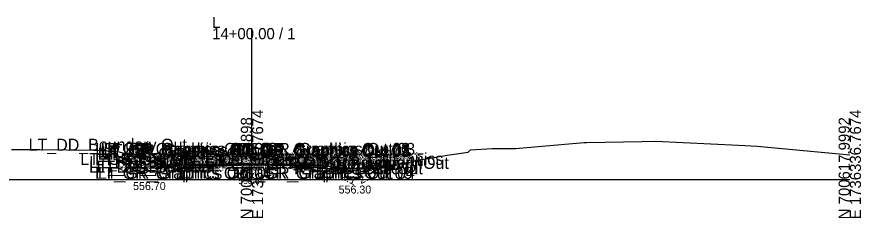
# Model space of a CAD drawing. Extents: x -26 to 697, y -10 to 2642.
# Drawn here: x 91 to 302.8, y 2390.3 to 2440.7 of the extents above; entities that cross this region are included whole.
import ezdxf

# ---------------------------------------------------------------- set-up
doc = ezdxf.new("R2010")
doc.units = 0
for name, color, linetype in [('Default', 7, 'Continuous'), ('Exist CMT Pavement', 7, 'Continuous'), ('Exist Cross Section Cell', 7, 'Continuous'), ('Exist XS Center Line Elevation Label', 7, 'Continuous'), ('Exist XS Ground Line', 7, 'Continuous'), ('Prop CMT Ditch DDE', 7, 'Continuous'), ('Prop CMT Guardrail Graphics', 7, 'Continuous'), ('Prop CMT Pvmt Course 1', 7, 'Continuous'), ('Prop CMT Pvmt Course 1 Wedge', 7, 'Continuous'), ('Prop CMT Pvmt Course 2', 7, 'Continuous'), ('Prop CMT Pvmt Course 2 Wedge', 7, 'Continuous'), ('Prop CMT Pvmt Surface', 7, 'Continuous'), ('Prop CMT Pvmt Surface Shoulder', 7, 'Continuous'), ('Prop CMT Pvmt Wedge Surface 1', 7, 'Continuous'), ('Prop CMT Pvmt Wedge Surface 2', 7, 'Continuous'), ('Prop CMT Shld Paved Course 1', 7, 'Continuous'), ('Prop CMT Shld Paved Course 2', 7, 'Continuous'), ('Prop CMT Slope Grass', 7, 'Continuous'), ('Prop CMT Subgrade Earthwork', 7, 'Continuous'), ('Prop XS Ditch Slope Text', 7, 'Continuous'), ('Prop XS Ditch Standard Text', 7, 'Continuous'), ('Prop XS SE Text', 7, 'Continuous'), ('Prop XS Side Slope Text', 7, 'Continuous'), ('Scratch_Level_1', 7, 'Continuous')]:
    doc.layers.add(name, color=color, linetype=linetype)

msp = doc.modelspace()

# ---------------------------------------------------------------- linework, layer by layer
at = {"layer": 'Exist CMT Pavement'}
for points in [[(150, 2403.64), (140.23, 2403.41)], [(140.23, 2403.41), (145.12, 2403.54)], [(145.12, 2403.54), (150, 2403.64)], [(154.78, 2403.6), (150, 2403.64)], [(150, 2403.64), (159.56, 2403.56)], [(159.56, 2403.56), (154.78, 2403.6)]]:
    msp.add_lwpolyline(points, dxfattribs=at)
at = {"layer": 'Exist Cross Section Cell'}
for p, q in [((150, 2400), (150, 2437.94)), ((0, 2400), (150, 2400)), ((150, 2400), (300, 2400))]:
    msp.add_line(p, q, dxfattribs=at)
at = {"layer": 'Exist XS Ground Line'}
msp.add_lwpolyline([(89.62, 2407.5), (96.35, 2407.5), (96.79, 2407.48), (110.3, 2407.33), (113.86, 2407.2), (116.66, 2406.93), (126.39, 2404.1), (132.44, 2402.17), (133.66, 2402.5), (135.83, 2403.03), (138.5, 2403.21), (140.23, 2403.41), (147.33, 2403.6), (149.81, 2403.64), (152.37, 2403.62), (159.56, 2403.56), (161.48, 2403.39), (162.65, 2403.28), (163.39, 2403.11), (167.5, 2402), (170.95, 2402.75), (171.39, 2402.77), (181, 2402.6), (190.42, 2404.47), (191.73, 2404.87), (193.73, 2405.2), (198.95, 2406.12), (204.27, 2406.86), (204.81, 2407.38), (210.28, 2407.71), (216.16, 2407.72), (232.35, 2409.18), (233.37, 2409.22), (234.04, 2409.25), (247.79, 2409.53), (251.23, 2409.57), (272.11, 2408.62), (276.72, 2408.36), (300, 2406.19)], dxfattribs=at)
at = {"layer": 'Prop CMT Ditch DDE'}
for points in [[(124.63, 2401.7), (113.62, 2407.2)], [(130.01, 2402.95), (127.01, 2402.89), (124.63, 2401.7)], [(170.58, 2402.67), (173.58, 2402.61), (176.2, 2401.3)], [(176.2, 2401.3), (178.88, 2402.64)], [(124.63, 2401.7), (124.63, 2401.7)], [(176.2, 2401.3), (176.2, 2401.3)]]:
    msp.add_lwpolyline(points, dxfattribs=at)
at = {"layer": 'Prop CMT Guardrail Graphics'}
for points in [[(132.33, 2400.15), (132.33, 2406.15)], [(132.33, 2406.15), (133.66, 2406.15), (133.93, 2405.86)], [(133.93, 2405.27), (133.66, 2404.98), (132.99, 2404.98)], [(132.99, 2404.98), (132.99, 2400.15)], [(133.93, 2405.86), (133.66, 2405.57)], [(133.66, 2405.57), (133.93, 2405.27)], [(167.71, 2406.15), (166.38, 2406.15), (166.11, 2405.86)], [(166.11, 2405.86), (166.38, 2405.57)], [(166.38, 2405.57), (166.11, 2405.27)], [(166.11, 2405.27), (166.38, 2404.98), (167.04, 2404.98)], [(167.04, 2404.98), (167.04, 2400.15)], [(167.71, 2400.15), (167.71, 2406.15)], [(132.99, 2400.15), (132.33, 2400.15)], [(167.04, 2400.15), (167.71, 2400.15)]]:
    msp.add_lwpolyline(points, dxfattribs=at)
at = {"layer": 'Prop CMT Pvmt Course 1'}
for points in [[(150, 2403.97), (139, 2403.75)], [(139, 2403.75), (139, 2403.54)], [(139, 2403.54), (140.23, 2403.57)], [(140.23, 2403.67), (150, 2403.87)], [(140.23, 2403.57), (140.23, 2403.67)], [(150, 2403.76), (150, 2403.97)], [(150, 2403.97), (161, 2403.75)], [(150, 2403.76), (150, 2403.97)], [(150, 2403.87), (150, 2403.76), (150, 2403.76)], [(159.56, 2403.68), (150, 2403.87)], [(150, 2403.87), (150, 2403.76), (150, 2403.76)], [(159.56, 2403.57), (159.56, 2403.68)], [(161, 2403.54), (159.56, 2403.57)], [(161, 2403.75), (161, 2403.54)]]:
    msp.add_lwpolyline(points, dxfattribs=at)
at = {"layer": 'Prop CMT Pvmt Course 1 Wedge'}
for points in [[(150, 2403.87), (140.23, 2403.67)], [(150, 2403.87), (159.56, 2403.68)]]:
    msp.add_lwpolyline(points, dxfattribs=at)
at = {"layer": 'Prop CMT Pvmt Course 2'}
for points in [[(140.23, 2403.57), (139, 2403.54)], [(139, 2403.54), (139, 2403.09)], [(139, 2403.09), (140.23, 2403.11)], [(140.23, 2403.11), (140.23, 2403.57)], [(159.56, 2403.11), (159.56, 2403.57)], [(159.56, 2403.57), (161, 2403.54)], [(161, 2403.09), (159.56, 2403.11)], [(161, 2403.54), (161, 2403.09)]]:
    msp.add_lwpolyline(points, dxfattribs=at)
at = {"layer": 'Prop CMT Pvmt Course 2 Wedge'}
for points in [[(150, 2403.76), (140.23, 2403.57)], [(150, 2403.76), (159.56, 2403.57)]]:
    msp.add_lwpolyline(points, dxfattribs=at)
at = {"layer": 'Prop CMT Pvmt Surface'}
for points in [[(150, 2403.97), (139, 2403.75)], [(150, 2403.97), (161, 2403.75)]]:
    msp.add_lwpolyline(points, dxfattribs=at)
at = {"layer": 'Prop CMT Pvmt Surface Shoulder'}
for points in [[(139, 2403.75), (133.94, 2403.65)], [(161, 2403.75), (166.1, 2403.65)]]:
    msp.add_lwpolyline(points, dxfattribs=at)
at = {"layer": 'Prop CMT Pvmt Wedge Surface 1'}
for points in [[(139, 2403.54), (139, 2403.75)], [(140.23, 2403.57), (139, 2403.54)], [(150, 2403.87), (140.23, 2403.67)], [(140.23, 2403.67), (140.23, 2403.57)], [(150, 2403.97), (150, 2403.76), (150, 2403.76), (150, 2403.87)], [(150, 2403.97), (150, 2403.76), (150, 2403.76), (150, 2403.87)], [(150, 2403.87), (159.56, 2403.68)], [(159.56, 2403.68), (159.56, 2403.57)], [(159.56, 2403.57), (161, 2403.54)], [(161, 2403.54), (161, 2403.75)]]:
    msp.add_lwpolyline(points, dxfattribs=at)
at = {"layer": 'Prop CMT Pvmt Wedge Surface 2'}
for points in [[(150, 2403.76), (139, 2403.54)], [(139, 2403.54), (139, 2403.75)], [(150, 2403.97), (150, 2403.76)], [(150, 2403.97), (150, 2403.76)], [(150, 2403.76), (161, 2403.54)], [(161, 2403.54), (161, 2403.75)]]:
    msp.add_lwpolyline(points, dxfattribs=at)
at = {"layer": 'Prop CMT Shld Paved Course 1'}
for points in [[(139, 2403.75), (133.94, 2403.65), (133.73, 2403.44)], [(133.73, 2403.44), (139, 2403.54)], [(139, 2403.54), (139, 2403.75)], [(161, 2403.75), (166.1, 2403.65), (166.31, 2403.44)], [(161, 2403.54), (161, 2403.75)], [(166.31, 2403.44), (161, 2403.54)]]:
    msp.add_lwpolyline(points, dxfattribs=at)
at = {"layer": 'Prop CMT Shld Paved Course 2'}
for points in [[(139, 2403.54), (133.73, 2403.44), (133.72, 2403.44), (133.25, 2402.97)], [(133.25, 2402.97), (139, 2403.09)], [(139, 2403.09), (139, 2403.54)], [(161, 2403.54), (166.31, 2403.44), (166.32, 2403.44), (166.79, 2402.97)], [(161, 2403.09), (161, 2403.54)], [(166.79, 2402.97), (161, 2403.09)]]:
    msp.add_lwpolyline(points, dxfattribs=at)
at = {"layer": 'Prop CMT Slope Grass'}
for points in [[(130.93, 2403.41), (130.01, 2402.95)], [(133.93, 2403.65), (130.93, 2403.41)], [(133.94, 2403.65), (133.93, 2403.65)], [(166.1, 2403.65), (166.11, 2403.65)], [(166.11, 2403.65), (169.11, 2403.41)], [(169.11, 2403.41), (170.58, 2402.67)]]:
    msp.add_lwpolyline(points, dxfattribs=at)
at = {"layer": 'Prop CMT Subgrade Earthwork'}
for points in [[(133.25, 2402.97), (132.67, 2403.55)], [(139, 2403.09), (133.25, 2402.97)], [(140.23, 2403.11), (139, 2403.09)], [(140.23, 2403.11), (140.25, 2403.41)], [(159.56, 2403.11), (159.55, 2403.57)], [(159.56, 2403.11), (161, 2403.09)], [(161, 2403.09), (166.79, 2402.97)], [(166.79, 2402.97), (167.36, 2403.55)]]:
    msp.add_lwpolyline(points, dxfattribs=at)
at = {"layer": 'Scratch_Level_1'}
for p, q in [((150, 2403.87), (140.23, 2403.67)), ((140.23, 2403.67), (140.23, 2403.57)), ((140.23, 2403.57), (140.23, 2403.45)), ((145.96, 2403.56), (140.23, 2403.45)), ((140.23, 2403.45), (145.96, 2403.56)), ((140.23, 2403.45), (140.23, 2403.41)), ((140.23, 2403.41), (140.25, 2403.41)), ((140.25, 2403.41), (145.12, 2403.54)), ((145.12, 2403.54), (145.96, 2403.56)), ((149.98, 2403.64), (150, 2403.64)), ((159.56, 2403.68), (150, 2403.87)), ((150, 2403.87), (150, 2403.76)), ((150, 2403.76), (150, 2403.87)), ((150, 2403.64), (150.01, 2403.64)), ((159.55, 2403.57), (159.56, 2403.56)), ((159.56, 2403.57), (159.56, 2403.68)), ((159.56, 2403.56), (159.56, 2403.57))]:
    msp.add_line(p, q, dxfattribs=at)
for points in [[(145.96, 2403.56), (147.33, 2403.6), (149.81, 2403.64), (149.98, 2403.64)], [(150.01, 2403.64), (150.01, 2403.64)], [(150.01, 2403.64), (152.37, 2403.62), (154.78, 2403.6), (159.55, 2403.57)]]:
    msp.add_lwpolyline(points, dxfattribs=at)

# ---------------------------------------------------------------- texts
at = {"layer": 'Default'}
for s, p in [('LT_DD_Boundary Out', (93.96, 2407.2)), ('LT_GR_Graphics Out 03', (110.68, 2406.15)), ('LT_GR_Graphics Out 09', (111.99, 2405.57)), ('LT_GR_Graphics Out 02', (112.07, 2406.15)), ('LT_GR_Graphics Out 01', (112.77, 2405.86)), ('RT_GR_Graphics Out 09', (144.53, 2405.57)), ('RT_GR_Graphics Out 02', (144.61, 2406.15)), ('RT_GR_Graphics Out 01', (144.77, 2405.86)), ('RT_GR_Graphics Out 03', (145.89, 2406.15)), ('LT_GS_OS_GR_Face_Graphics', (106.92, 2403.65)), ('LT_Sub_Trench_Out_DLT', (110.62, 2403.55)), ('LT_GR_Graphics Out 06', (111.31, 2404.98)), ('LT_GR_Graphics Out 07', (111.94, 2404.98)), ('LT_GR_Graphics Out 08', (112.25, 2405.27)), ('LT_GS_OS_CTL', (117.32, 2403.41)), ('LT_PS2_Shelf_Out', (117.69, 2403.44)), ('LT_PS2_OEOP', (121.09, 2403.44)), ('LT_PS1_OEOP', (121.66, 2403.65)), ('LT_PV_Sub_Tie_Out', (122.74, 2403.41)), ('LT_PV_OEEOP_EG', (124.03, 2403.41)), ('LT_PV2_OEOT', (126.24, 2403.54)), ('LT_PV2_OEEOP', (126.41, 2403.57)), ('LT_PV1_OEOT', (126.6, 2403.75)), ('LT_PV1_OEEOP', (126.77, 2403.67)), ('LT_PV_EG_TestPt', (130.24, 2403.54)), ('RT_PV_IEEOP_EG', (134.76, 2403.64)), ('LT_PV_IEEOP_EG', (134.93, 2403.64)), ('RT_PV2_IEEOP', (137.14, 2403.76)), ('LT_PV2_IEEOP', (137.32, 2403.76)), ('RT_PV1_IEEOP', (137.5, 2403.87)), ('LT_PV1_IEEOP', (137.68, 2403.87)), ('RT_GS_OS_GR_Face_Graphics', (138.92, 2403.65)), ('RT_PV_EG_TestPt', (139.72, 2403.6)), ('RT_PV_Sub_Tie_Out', (141.86, 2403.57)), ('PV2_PGL', (142.05, 2403.76)), ('PV1_PGL', (142.41, 2403.97)), ('RT_PV_OEEOP_EG', (143.18, 2403.56)), ('RT_GR_Graphics Out 08', (144.24, 2405.27)), ('RT_GR_Graphics Out 07', (144.48, 2404.98)), ('RT_Sub_Trench_Out_DLT', (145.14, 2403.55)), ('RT_GR_Graphics Out 06', (145.19, 2404.98)), ('RT_PV2_OEEOP', (145.56, 2403.57)), ('RT_PV1_OEEOP', (145.92, 2403.68)), ('RT_PV2_OEOT', (148.06, 2403.54)), ('RT_PV1_OEOT', (148.42, 2403.75)), ('RT_PS2_Shelf_Out', (150.11, 2403.44)), ('RT_PS2_OEOP', (153.49, 2403.44)), ('RT_PS1_OEOP', (153.64, 2403.65)), ('RT_GS_OS_CTL', (155.32, 2403.41)), ('LT_DD_Base Out', (109.13, 2401.7)), ('LT_DD_Boundary In', (109.18, 2402.89)), ('LT_DD_Base In', (110.97, 2401.7)), ('LT_Sub_Trench_Out', (115.58, 2402.97)), ('LT_Slope_Fill', (118.72, 2402.95)), ('LT_Slope_Fill', (118.72, 2402.95)), ('LT_Sub_OEOT', (126.31, 2403.09)), ('LT_Sub_OEEOP', (126.48, 2403.11)), ('RT_Sub_OEEOP', (145.63, 2403.11)), ('RT_Sub_OEOT', (148.13, 2403.09)), ('RT_Sub_Trench_Out', (148.94, 2402.97)), ('RT_DD_Boundary In', (155.58, 2402.61)), ('RT_DD_Boundary Out', (159.04, 2402.64)), ('RT_Slope_Fill', (159.12, 2402.67)), ('RT_Slope_Fill', (159.12, 2402.67)), ('RT_DD_Base Out', (160.53, 2401.3)), ('RT_DD_Base In', (162.36, 2401.3)), ('LT_GR_Graphics Out 04', (110.64, 2400.15)), ('LT_GR_Graphics Out 05', (111.33, 2400.15)), ('RT_GR_Graphics Out 05', (145.2, 2400.15)), ('RT_GR_Graphics Out 04', (145.84, 2400.15))]:
    msp.add_text(s, height=3, dxfattribs=at).set_placement(p)
at = {"layer": 'Exist Cross Section Cell'}
for s, p in [('L', (140, 2437.94)), ('14+00.00 / 1', (140, 2435.14))]:
    msp.add_text(s, height=2.8, dxfattribs=at).set_placement(p)
for s, p in [('E 1736190.7674', (152.8, 2390)), ('E 1736336.7674', (302.8, 2390)), ('N 700583.5898', (150, 2390)), ('N 700617.9992', (300, 2390))]:
    msp.add_text(s, height=2.8, rotation=90, dxfattribs=at).set_placement(p)
at = {"layer": 'Exist XS Center Line Elevation Label'}
msp.add_text('558.64', height=1.6, dxfattribs=at).set_placement((146.58, 2398.84))
at = {"layer": 'Prop XS Ditch Slope Text'}
for rotation, p in [(333.4349, (116.48, 2402.7)), (26.5651, (126.25, 2399.61)), (333.4349, (172.25, 2400.21)), (26.5651, (177.35, 2398.8))]:
    msp.add_text('2:1', height=2, rotation=rotation, dxfattribs=at).set_placement(p)
at = {"layer": 'Prop XS Ditch Standard Text'}
for s, p in [('556.70', (120.16, 2397.34)), ('556.30', (171.74, 2396.47))]:
    msp.add_text(s, height=2, dxfattribs=at).set_placement(p)
at = {"layer": 'Prop XS SE Text'}
for rotation, p in [(1.1458, (140.98, 2404.79)), (358.8542, (152.02, 2404.93))]:
    msp.add_text('0.020', height=2, rotation=rotation, dxfattribs=at).set_placement(p)
at = {"layer": 'Prop XS Side Slope Text'}
for rotation, p in [(26.5525, (128.72, 2403.14)), (333.4349, (168.76, 2404.42))]:
    msp.add_text('2:1', height=2, rotation=rotation, dxfattribs=at).set_placement(p)

doc.saveas('drawing.dxf')
